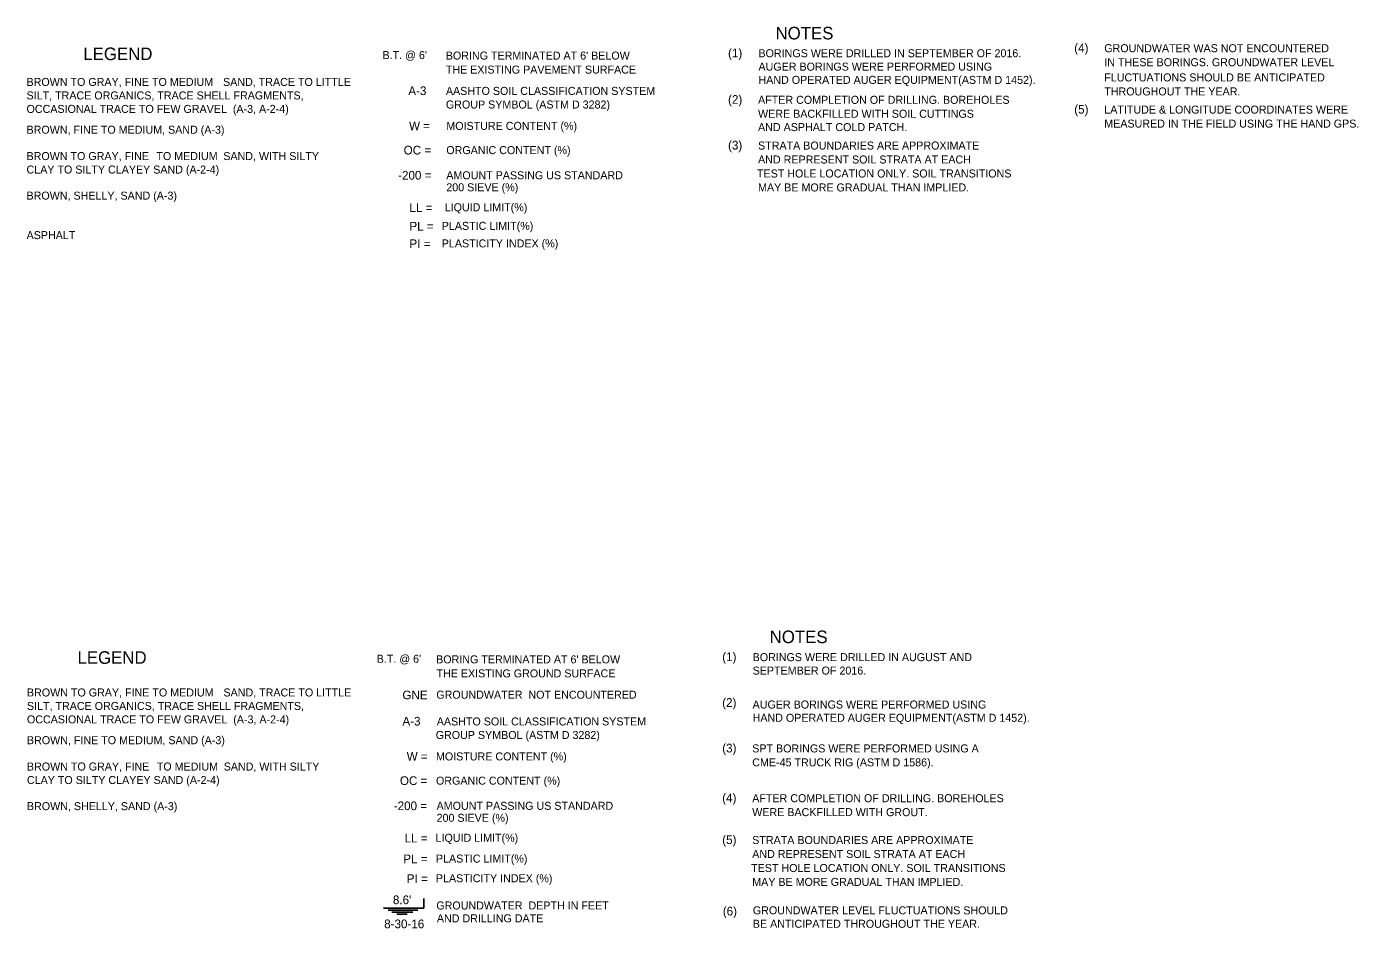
# Model space of a CAD drawing. Extents: x 0 to 331, y -72 to 117.
# Drawn here: x 71.29 to 94.58, y -72.12 to -56.34 of the extents above; entities that cross this region are included whole.
import ezdxf

# ---------------------------------------------------------------- set-up
doc = ezdxf.new("R2010")
doc.units = 0
doc.layers.add('1-TEXT', color=7, linetype='Continuous')

msp = doc.modelspace()

# ---------------------------------------------------------------- linework, layer by layer
at = {"layer": '1-TEXT'}
for p, q in [((78.233, -71.767), (78.233, -71.597)), ((77.529, -71.767), (78.233, -71.767)), ((77.61, -71.802), (78.129, -71.802)), ((77.674, -71.836), (78.043, -71.836)), ((77.761, -71.871), (77.941, -71.871))]:
    msp.add_line(p, q, dxfattribs=at)

# ---------------------------------------------------------------- texts
for s, height, p in [('NOTES', 0.22, (84.387, -56.568)), ('LEGEND', 0.22, (72.277, -56.93)), ("B.T. @ 6'", 0.14, (77.512, -56.912)), ("BORING TERMINATED AT 6' BELOW", 0.14, (78.619, -56.921)), ('(1)', 0.1521, (83.557, -56.883)), ('BORINGS WERE DRILLED IN SEPTEMBER OF 2016.', 0.14, (84.089, -56.88)), ('(4)', 0.1521, (89.614, -56.792)), ('GROUNDWATER WAS NOT ENCOUNTERED  ', 0.14, (90.139, -56.792)), ('THE EXISTING PAVEMENT SURFACE', 0.14, (78.619, -57.166)), ('AUGER BORINGS WERE PERFORMED USING', 0.14, (84.089, -57.114)), ('IN THESE BORINGS. GROUNDWATER LEVEL', 0.14, (90.139, -57.037)), ('BROWN TO GRAY, FINE TO MEDIUM', 0.14, (71.284, -57.382)), ('SAND, TRACE TO LITTLE ', 0.14, (74.722, -57.382)), ('HAND OPERATED AUGER EQUIPMENT(ASTM D 1452).', 0.14, (84.089, -57.346)), ('FLUCTUATIONS SHOULD BE ANTICIPATED ', 0.14, (90.139, -57.303)), ('SILT, TRACE ORGANICS, TRACE SHELL FRAGMENTS, ', 0.14, (71.284, -57.618)), ('A-3', 0.1521, (77.963, -57.542)), ('AASHTO SOIL CLASSIFICATION SYSTEM', 0.14, (78.621, -57.539)), ('(2)', 0.1521, (83.557, -57.695)), ('THROUGHOUT THE YEAR.', 0.14, (90.139, -57.548)), ('OCCASIONAL TRACE TO FEW GRAVEL  (A-3, A-2-4)', 0.14, (71.284, -57.854)), ('GROUP SYMBOL (ASTM D 3282)', 0.14, (78.621, -57.777)), ('AFTER COMPLETION OF DRILLING. BOREHOLES', 0.14, (84.082, -57.695)), ('(5)', 0.1521, (89.614, -57.866)), ('LATITUDE & LONGITUDE COORDINATES WERE ', 0.14, (90.139, -57.866)), ('W =', 0.1521, (77.976, -58.157)), ('MOISTURE CONTENT (%)', 0.14, (78.628, -58.151)), ('WERE BACKFILLED WITH SOIL CUTTINGS ', 0.14, (84.082, -57.939)), ('MEASURED IN THE FIELD USING THE HAND GPS.', 0.14, (90.139, -58.111)), ('BROWN, FINE TO MEDIUM, SAND (A-3)', 0.14, (71.284, -58.218)), ('AND ASPHALT COLD PATCH.', 0.14, (84.082, -58.172)), ('OC =', 0.1521, (77.882, -58.581)), ('ORGANIC CONTENT (%)', 0.14, (78.628, -58.575)), ('(3)', 0.1521, (83.557, -58.495)), ('STRATA BOUNDARIES ARE APPROXIMATE', 0.14, (84.082, -58.495)), ('BROWN TO GRAY, FINE ', 0.14, (71.284, -58.679)), ('TO MEDIUM ', 0.14, (73.556, -58.679)), ('SAND, WITH SILTY ', 0.14, (74.726, -58.679)), ('AND REPRESENT SOIL STRATA AT EACH', 0.14, (84.082, -58.739)), ('CLAY TO SILTY CLAYEY SAND (A-2-4)', 0.14, (71.284, -58.915)), ('-200 =', 0.1521, (77.785, -59.021)), ('AMOUNT PASSING US STANDARD', 0.14, (78.628, -59.015)), ('TEST HOLE LOCATION ONLY. SOIL TRANSITIONS', 0.14, (84.063, -58.984)), ('200 SIEVE (%)', 0.14, (78.628, -59.225)), ('MAY BE MORE GRADUAL THAN IMPLIED.', 0.14, (84.082, -59.228)), ('BROWN, SHELLY, SAND (A-3) ', 0.14, (71.284, -59.371)), ('LL =', 0.1521, (77.983, -59.587)), (' LIQUID LIMIT(%%%)', 0.14, (78.548, -59.575)), ('PL =', 0.1521, (77.983, -59.912)), ('PLASTIC LIMIT(%%%)', 0.14, (78.548, -59.9)), ('ASPHALT', 0.14, (71.285, -60.062)), ('PI =', 0.1521, (77.983, -60.219)), ('PLASTICITY INDEX (%%%)', 0.14, (78.548, -60.207)), ('NOTES', 0.22, (84.285, -67.131)), ('LEGEND', 0.22, (72.175, -67.493)), ("B.T. @ 6'", 0.14, (77.41, -67.475)), ('(1)', 0.1521, (83.455, -67.446)), ('BORINGS WERE DRILLED IN AUGUST AND', 0.14, (83.987, -67.446)), ("BORING TERMINATED AT 6' BELOW", 0.14, (78.45, -67.485)), ('SEPTEMBER OF 2016.', 0.14, (83.987, -67.681)), ('THE EXISTING GROUND SURFACE', 0.14, (78.456, -67.73)), ('BROWN TO GRAY, FINE TO MEDIUM', 0.14, (71.291, -68.064)), ('SAND, TRACE TO LITTLE ', 0.14, (74.729, -68.064)), ('GNE', 0.1521, (77.86, -68.114)), ('GROUNDWATER  NOT ENCOUNTERED', 0.14, (78.453, -68.103)), ('SILT, TRACE ORGANICS, TRACE SHELL FRAGMENTS, ', 0.14, (71.291, -68.3)), ('(2)', 0.1521, (83.455, -68.246)), ('AUGER BORINGS WERE PERFORMED USING', 0.14, (83.987, -68.275)), ('OCCASIONAL TRACE TO FEW GRAVEL  (A-3, A-2-4)', 0.14, (71.291, -68.535)), ('A-3', 0.1521, (77.86, -68.573)), ('AASHTO SOIL CLASSIFICATION SYSTEM', 0.14, (78.461, -68.571)), ('HAND OPERATED AUGER EQUIPMENT(ASTM D 1452).', 0.14, (83.987, -68.507)), ('GROUP SYMBOL (ASTM D 3282)', 0.14, (78.443, -68.808)), ('BROWN, FINE TO MEDIUM, SAND (A-3)', 0.14, (71.291, -68.899)), ('(3)', 0.1521, (83.455, -69.043)), ('SPT BORINGS WERE PERFORMED USING A', 0.14, (83.98, -69.043)), ('W =', 0.1521, (77.935, -69.188)), ('MOISTURE CONTENT (%)', 0.14, (78.447, -69.183)), ('CME-45 TRUCK RIG (ASTM D 1586).', 0.14, (83.98, -69.287)), ('BROWN TO GRAY, FINE ', 0.14, (71.291, -69.36)), ('TO MEDIUM ', 0.14, (73.563, -69.36)), ('SAND, WITH SILTY ', 0.14, (74.733, -69.36)), ('CLAY TO SILTY CLAYEY SAND (A-2-4)', 0.14, (71.291, -69.596)), ('OC =', 0.1521, (77.816, -69.613)), ('ORGANIC CONTENT (%)', 0.14, (78.447, -69.607)), ('(4)', 0.1521, (83.455, -69.914)), ('AFTER COMPLETION OF DRILLING. BOREHOLES', 0.14, (83.98, -69.914)), ('BROWN, SHELLY, SAND (A-3) ', 0.14, (71.291, -70.053)), ('-200 =', 0.1521, (77.709, -70.053)), ('AMOUNT PASSING US STANDARD', 0.14, (78.458, -70.047)), ('200 SIEVE (%)', 0.14, (78.458, -70.257)), ('WERE BACKFILLED WITH GROUT. ', 0.14, (83.98, -70.158)), ('LL =', 0.1521, (77.898, -70.619)), (' LIQUID LIMIT(%%%)', 0.14, (78.388, -70.607)), ('(5)', 0.1521, (83.455, -70.646)), ('STRATA BOUNDARIES ARE APPROXIMATE', 0.14, (83.98, -70.646)), ('PLASTIC LIMIT(%%%)', 0.14, (78.446, -70.97)), ('AND REPRESENT SOIL STRATA AT EACH', 0.14, (83.98, -70.89)), ('PL =', 0.1521, (77.875, -70.982)), ('TEST HOLE LOCATION ONLY. SOIL TRANSITIONS', 0.14, (83.961, -71.135)), ('PI =', 0.1521, (77.936, -71.327)), ('PLASTICITY INDEX (%%%)', 0.14, (78.446, -71.315)), ('MAY BE MORE GRADUAL THAN IMPLIED.', 0.14, (83.98, -71.379)), ("  8.6'", 0.1521, (77.581, -71.698)), ('GROUNDWATER  DEPTH IN FEET', 0.14, (78.453, -71.791)), ('(6)', 0.1521, (83.465, -71.896)), ('GROUNDWATER LEVEL FLUCTUATIONS SHOULD', 0.14, (83.991, -71.876)), ('8-30-16', 0.1521, (77.541, -72.119)), ('AND DRILLING DATE', 0.14, (78.463, -72.016)), ('BE ANTICIPATED THROUGHOUT THE YEAR.', 0.14, (83.991, -72.111))]:
    msp.add_text(s, height=height, dxfattribs=at).set_placement(p)

doc.saveas('drawing.dxf')
